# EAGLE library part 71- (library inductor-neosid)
RF TRANSFORMER adjustable RF coil/transformer
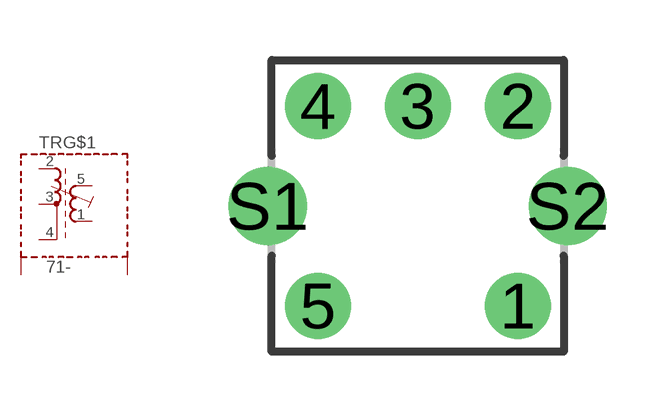
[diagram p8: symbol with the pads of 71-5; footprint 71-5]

Designator prefix TR; gates G$1=SMF51-42 G$2=SHIELD3

## 71-24513-2 (OC_FARNELL: unknown; OC_NEWARK: unknown)  [71-5]
1  G$1:E2  pas
2  G$1:A1  pas
3  G$1:Z  pas
4  G$1:E1  pas
5  G$1:A2  pas
S1  G$2:S1  pas
S2  G$2:S2  pas

## Footprint 71-5 (pad centres in mm)
RF COIL ASSEMBLY 1 winding, 5 pads, grid 2.5 mm
drill 1.1 round: 1 2.5,-2.5; 2 2.5,2.5; 3 0,2.5; 4 -2.5,2.5; 5 -2.5,-2.5
drill 1.3 round: S1 -3.75,0; S2 3.75,0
